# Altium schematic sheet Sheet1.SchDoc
size B; SheetNumber: 1; SheetTotal: 1
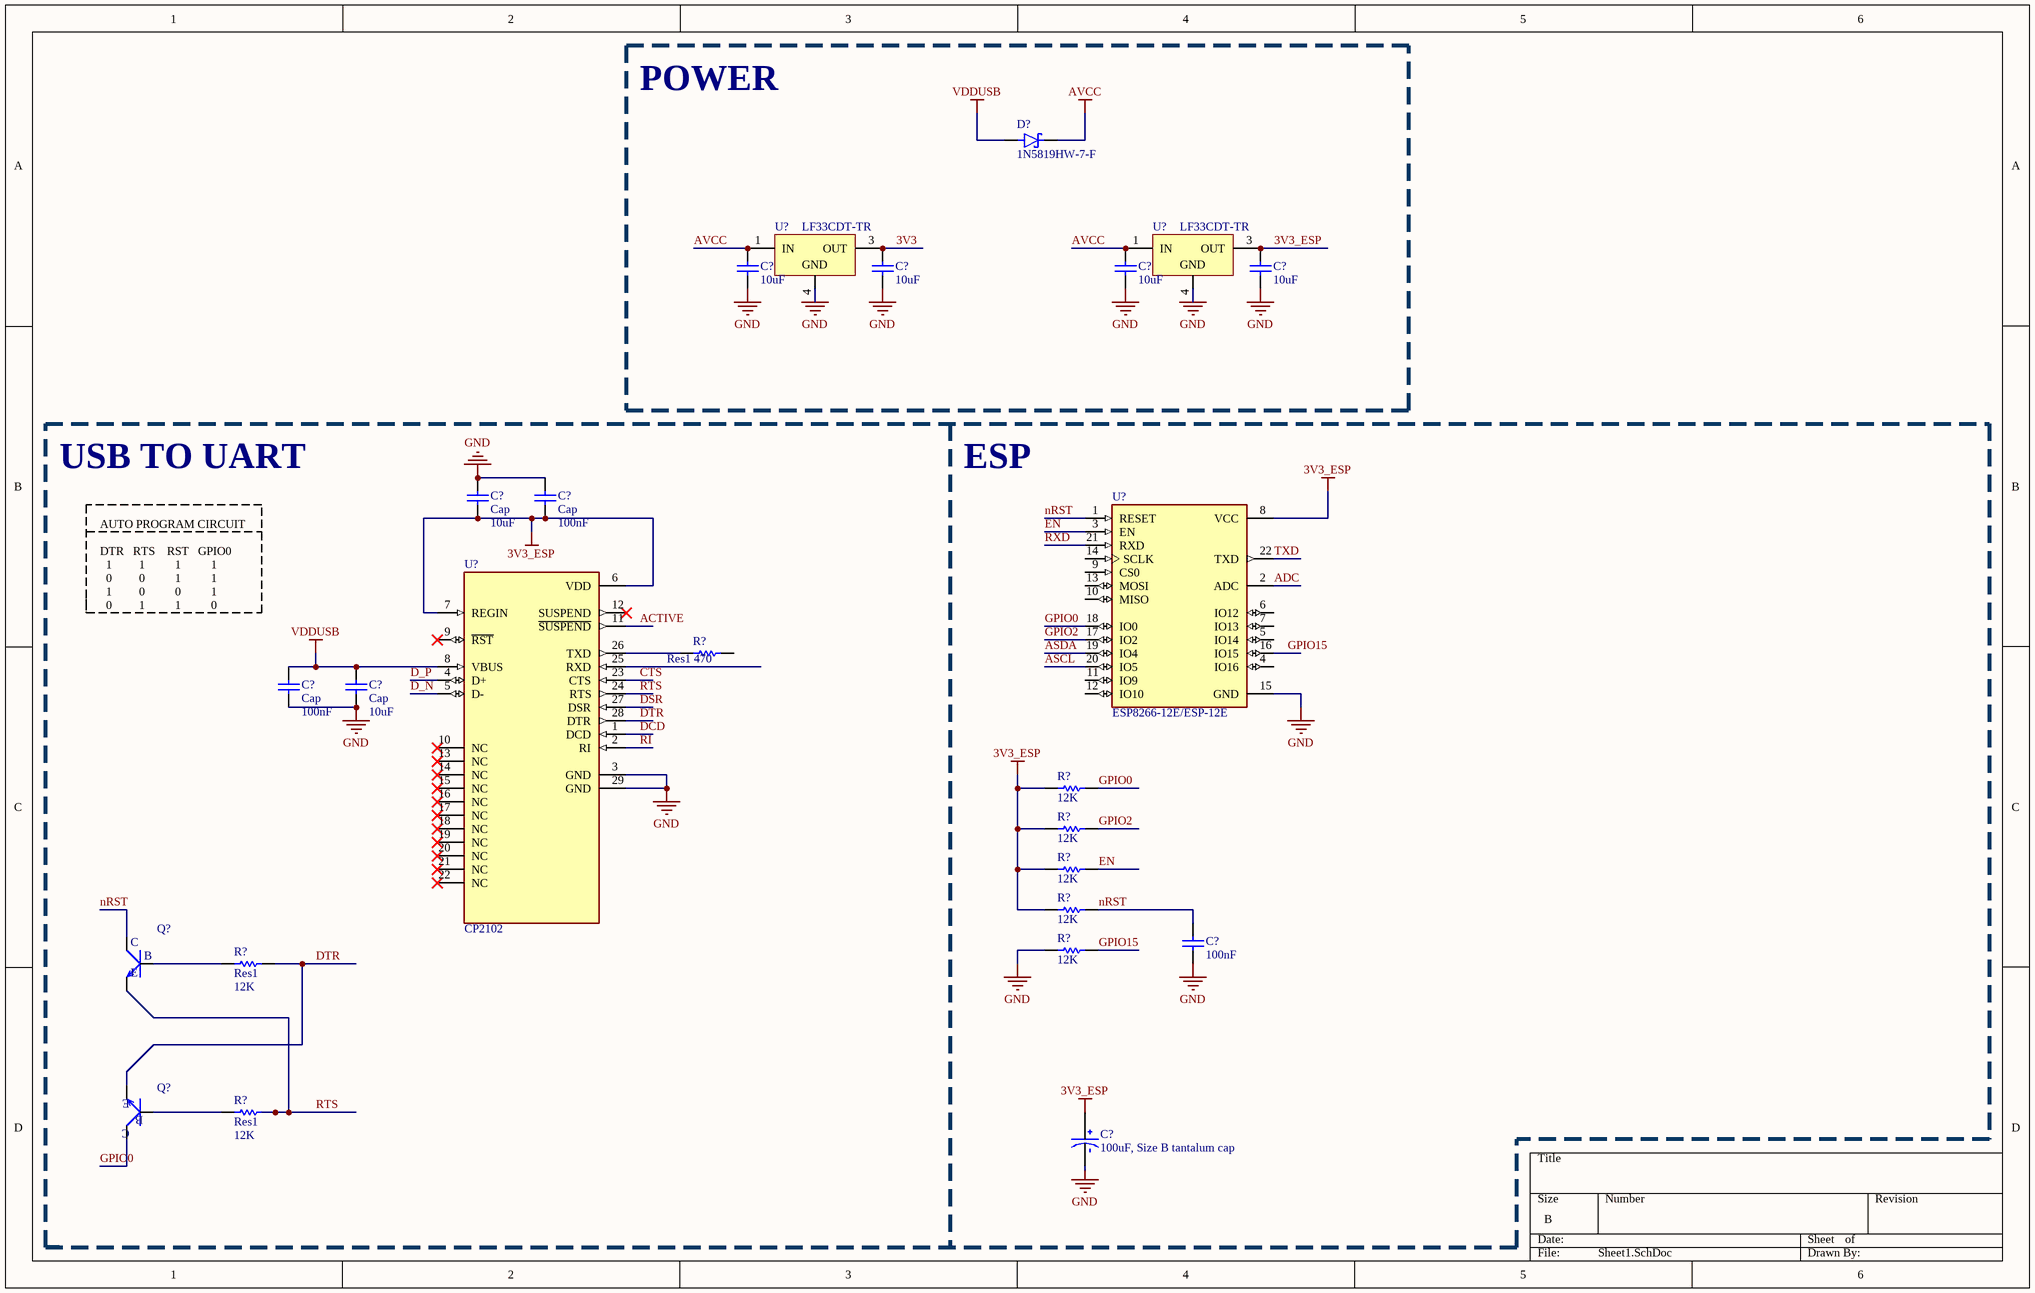
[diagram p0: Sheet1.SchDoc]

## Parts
(Parts that share a designator on the sheet are numbered #1, #2 ... from top to bottom, then left to right.)
C?#1  10uF  [CAP805]
C?#2  10uF  [CAP805]
C?#3  10uF  [CAP805]
C?#4  10uF  [CAP805]
C?#5  Cap  value 10uF  [RAD-0.3]
C?#6  Cap  value 100nF  [RAD-0.3]
C?#7  Cap  value 100nF  [RAD-0.3]
C?#8  Cap  value 10uF  [RAD-0.3]
C?#9  100nF  [CAP805]
C?#10  100uF, Size B tantalum cap  [CAPMC6032X260]
D?  1N5819HW-7-F  [SOD3715X145N]
Q?#1  SMD-TRANSISTORS-NPN-25V-500MW(SOT-23)  [SOT-23]  (value not drawn)
Q?#2  SMD-TRANSISTORS-NPN-25V-500MW(SOT-23)  [SOT-23]  (value not drawn)
R?#1  Res1  value 470  [AXIAL-0.3]
R?#2  12K  [RES0805]
R?#3  12K  [RES0805]
R?#4  12K  [RES0805]
R?#5  12K  [RES0805]
R?#6  Res1  value 12K  [AXIAL-0.3]
R?#7  12K  [RES0805]
R?#8  Res1  value 12K  [AXIAL-0.3]
U?#1  LF33CDT-TR  [TO-252_N]
U?#2  LF33CDT-TR  [TO-252_N]
U?#3  ESP8266-12E/ESP-12E  [XCVR_ESP8266-12E/ESP-12E]
U?#4  CP2102  [QFN50P500X500X100-29N]

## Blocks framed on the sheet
POWER: C?#1-C?#4 D? U?#1 U?#2

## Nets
3V3_ESP: C?#4.2 C?#5.2 C?#6.2 C?#10.POS R?#2.1 R?#3.1 R?#4.1 R?#5.1 U?#2.3(OUT) U?#3.8(VCC) U?#4.6(VDD) U?#4.7(REGIN)
AVCC: C?#1.2 C?#3.2 D?.C(K) U?#1.1(IN) U?#2.1(IN)
GND: C?#1.1 C?#2.1 C?#3.1 C?#4.1 C?#5.1 C?#6.1 C?#7.1 C?#8.1 C?#9.1 C?#10.NEG R?#7.1 U?#1.4(GND) U?#2.4(GND) U?#3.15(GND) U?#4.3(GND) U?#4.29(GND)
VDDUSB: C?#7.2 C?#8.2 D?.A U?#4.8(VBUS)
3V3: C?#2.2 U?#1.3(OUT)
ACTIVE: U?#4.11(~{SUSPEND})
ADC: U?#3.2(ADC)
ASCL: U?#3.20(IO5)
ASDA: U?#3.19(IO4)
CTS: U?#4.23(CTS)
D_N: U?#4.5(D-)
D_P: U?#4.4(D+)
DCD: U?#4.1(DCD)
DSR: U?#4.27(DSR)
DTR: Q?#2.2(E) R?#6.2 U?#4.28(DTR)
EN: R?#4.2 U?#3.3(EN)
GPIO0: Q?#2.3(C) R?#2.2 U?#3.18(IO0)
GPIO2: R?#3.2 U?#3.17(IO2)
GPIO15: R?#7.2 U?#3.16(IO15)
nRST: C?#9.2 Q?#1.3(C) R?#5.2 U?#3.1(RESET)
RI: U?#4.2(RI)
RTS: Q?#1.2(E) R?#8.2 U?#4.24(RTS)
RXD: U?#3.21(RXD)
TXD: U?#3.22(TXD)
NetQ?#1_1: Q?#1.1(B) R?#6.1
NetQ?#2_1: Q?#2.1(B) R?#8.1
NetR?#1_1: R?#1.1 U?#4.26(TXD)

Not connected (* = marked no-connect by the designer): R?#1 2; U?#3 4(IO16) 5(IO14) 6(IO12) 7(IO13) 9(CS0) 10(MISO) 11(IO9) 12(IO10) 13(MOSI) 14(SCLK); U?#4 9(~{RST})* 10(NC)* 12(SUSPEND)* 13(NC)* 14(NC)* 15(NC)* 16(NC)* 17(NC)* 18(NC)* 19(NC)* 20(NC)* 21(NC)* 22(NC)* 25(RXD)

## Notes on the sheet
- USB TO UART
- ESP
- AUTO PROGRAM CIRCUIT
  DTR   RTS    RST   GPIO0
  1         1          1          1
  0         0          1          1
  1         0          0          1
  0         1          1          0

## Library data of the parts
C?#1-C?#4 C?#9 = CAP SMD PACKAGE: TOTAL CAPACITOR SMD PACK; Designer: Abbas Basereh; Desc.: CAP SMD TOTAL PACKAGES
C?#5-C?#8 = Cap: Capacitor
C?#10 = TAJC107K016RNJ: 100µF Molded Tantalum Capacitors 16V 2312 _6032 Metric_ 1Ohm; MF: AVX Interconnect / Elco
D? = 1N5819HW-7-F: Diode Schottky 40 V 1A Surface Mount SOD-123; MF: Diodes Inc.
Q?#1 Q?#2 = SMD-TRANSISTORS-NPN-25V-500MW(SOT-23): Bipolar (BJT) Transistor NPN 25 V 500 mA 150MHz 300 mW Surface Mount SOT-23; MF: UMW; MP: S8050
R?#1 R?#6 R?#8 = Res1: Resistor
R?#2-R?#5 R?#7 = RES SMD PACKAGE: TOTAL SMD RESISTOR PACK; Designer: Abbas Basereh; Desc.: RES SMD PAKAGES
U?#1 U?#2 = LF33CDT-TR: 500mA, Very Low Drop (0.45V) Voltage Regulator, 3.3V, 3-Pin DPAK, Tape and Reel
U?#3 = ESP8266-12E/ESP-12E: This WiFi module has a 32-bit MCU micro and clock speeds supporting 80 MHz or 160 MHz. Supports the RTOS and integrated Wi-Fi MAC/BB/RF/PA/LNA, and has an on-board antenna.; MF: AI-Thinker
U?#4 = CP2102: CP2102N USB 2.0 to UART (RS232) Bridge Interface Evaluation Board; MF: Silicon Labs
